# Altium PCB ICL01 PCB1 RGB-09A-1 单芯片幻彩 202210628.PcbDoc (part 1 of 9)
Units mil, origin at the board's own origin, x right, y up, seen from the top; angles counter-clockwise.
Board outline 17436.43 x 6581.89 mil, 2 copper layers (Top Layer, Bottom Layer), stack 65.792 mil thick; 425 components, 516 nets, 1625 pads, 2772 vias.
Unrouted connection lines stored in the file: 1.
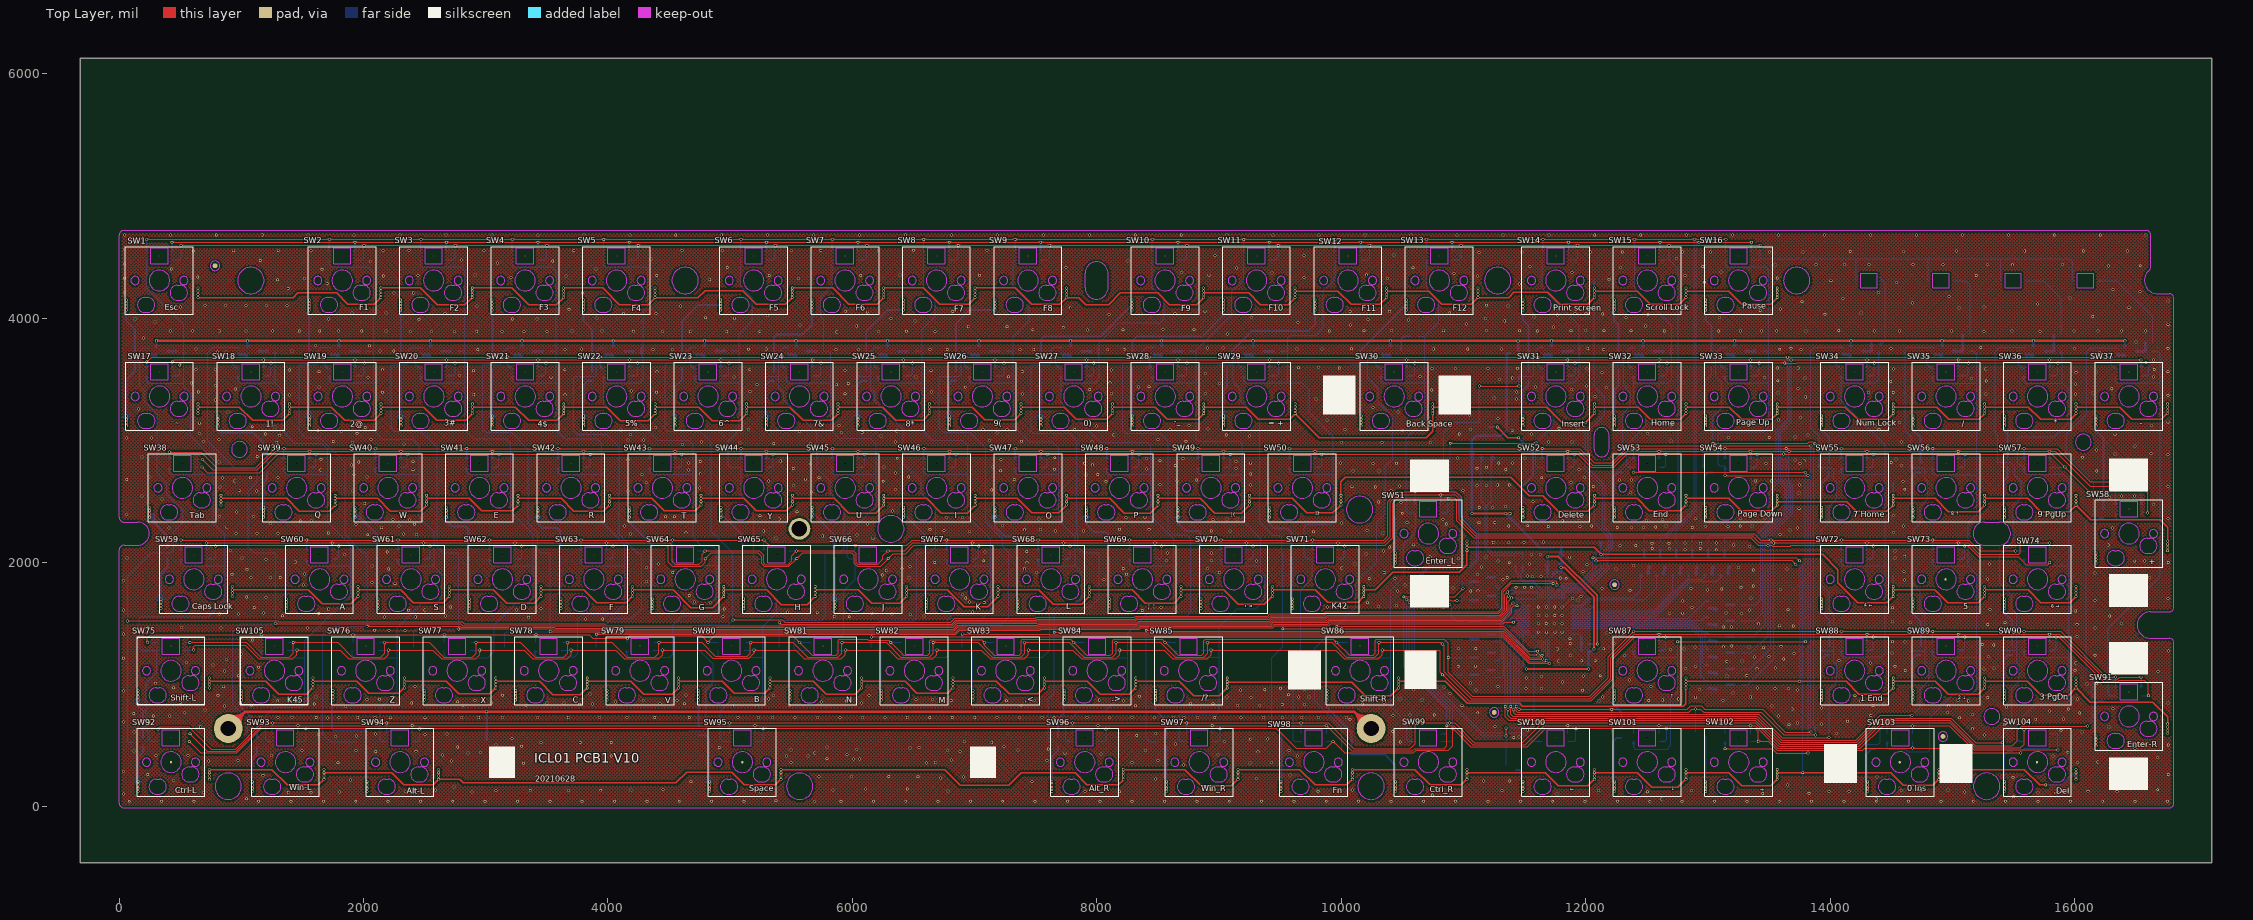
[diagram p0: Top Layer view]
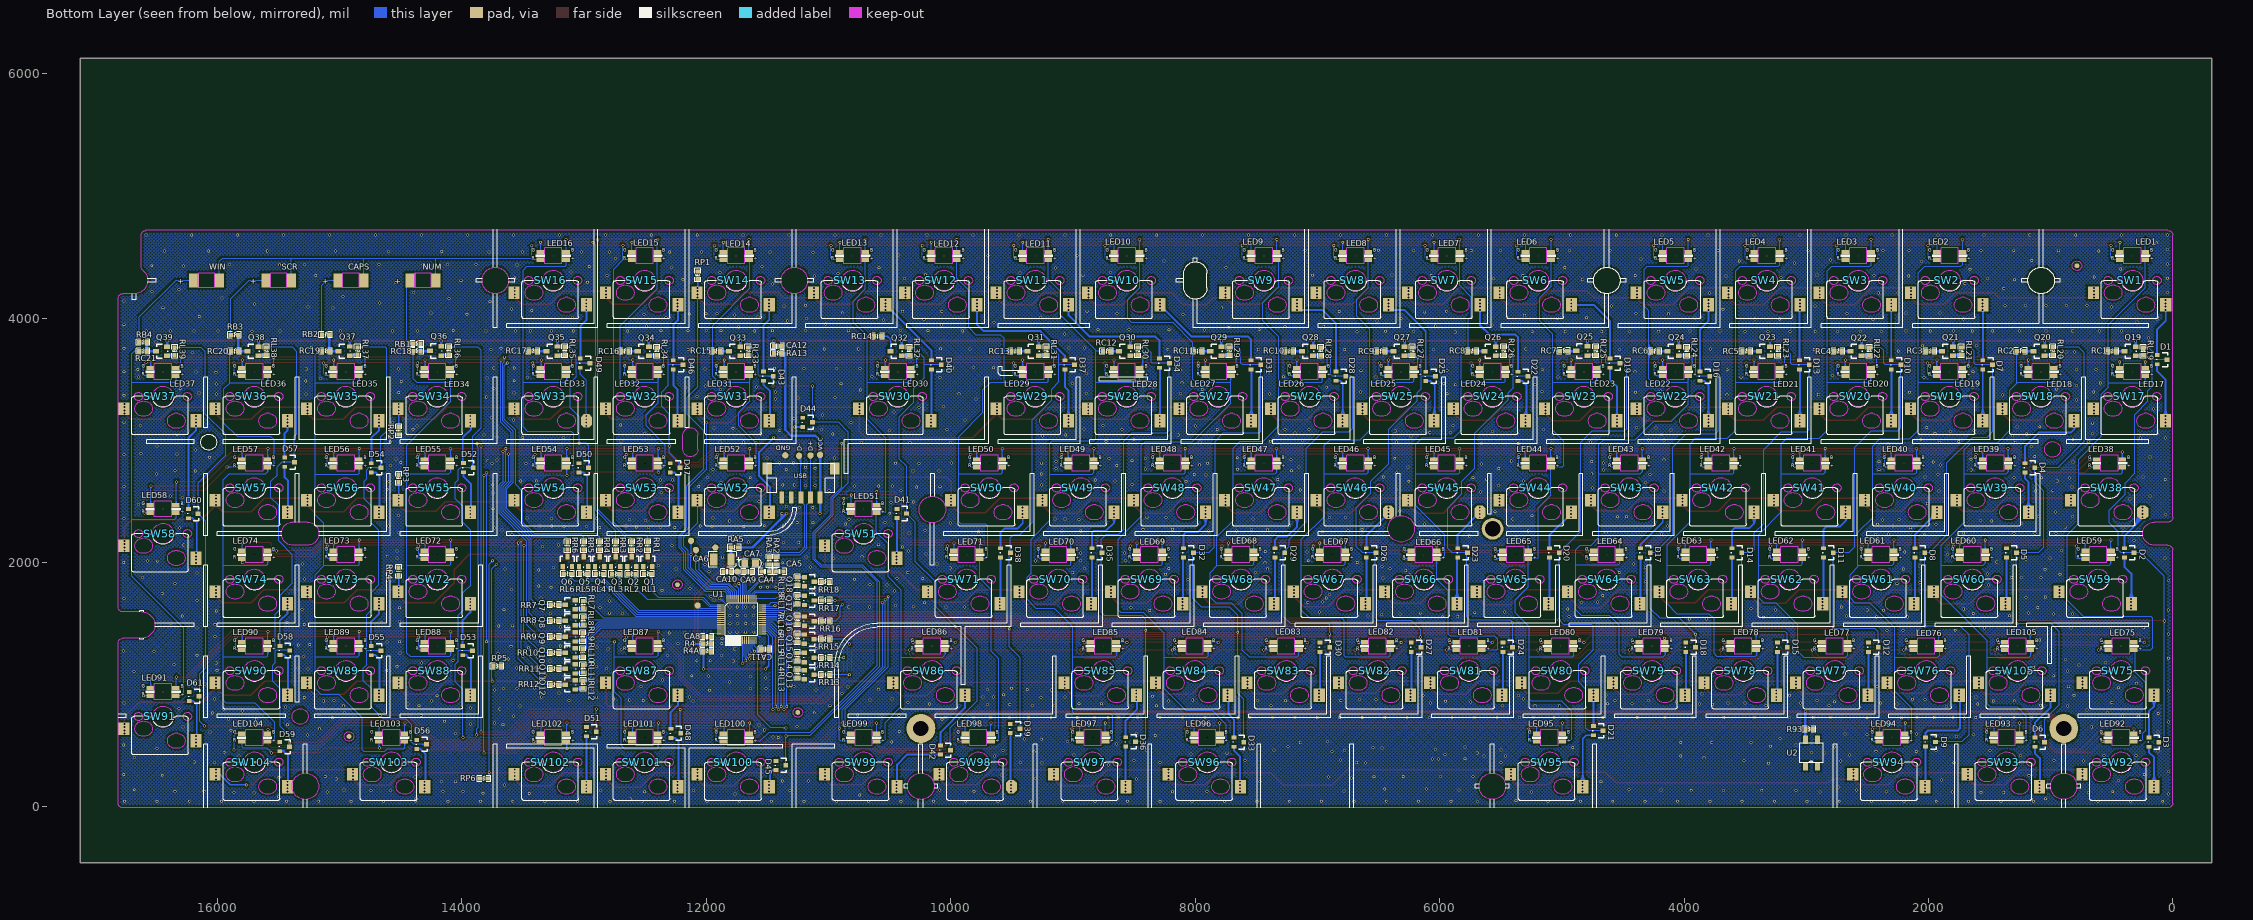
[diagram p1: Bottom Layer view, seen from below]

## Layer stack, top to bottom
Top Solder: solder mask 0.4, Solder Resist, Dk 3.5
Top Layer: signal copper 1.4
Dielectric 1: dielectric 62.9921, FR-4, Dk 4.8
Bottom Layer: signal copper 1.4
Bottom Solder: solder mask 0.4, Solder Resist, Dk 3.5

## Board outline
-315.78,-457.77 -315.78,6124.12 17120.64,6124.12 17120.64,-457.77

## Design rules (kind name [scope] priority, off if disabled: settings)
Clearance [All] p1: gap=6
ComponentClearance [All] p1 off: gap=10 collisioncheckmode=3 verticalgap=10 showdistances=FALSE
DiffPairsRouting [All] p1: maxlimit=9.84 minlimit=9.84 mostfreqgap=9.84 toplayer_minwidth=9.84 toplayer_maxwidth=9.84 toplayer_prefwidth=9.84 bottomlayer_minwidth=9.84 bottomlayer_maxwidth=9.84 bottomlayer_prefwidth=9.84 maxuncoupledlength=500
PlaneClearance [All] p1: clearance=19.68
PolygonConnect PolygonConnect_1 [ISVIA] p1: connectstyle=Direct reliefconductorwidth=10 reliefentries=4 polygonreliefangle="90 Angle" airgapwidth=10
PolygonConnect [All] p2: connectstyle=Relief reliefconductorwidth=10 reliefentries=4 polygonreliefangle="90 Angle" airgapwidth=10
RoutingVias [All] p1: holewidth=15.75 width=23.62 viastyle="Through Hole" minholewidth=15.75 minwidth=23.62 maxholewidth=15.75 maxwidth=23.62
SolderMaskExpansion [All] p1: expansion=4
Width [All] p1: maxlimit=78.74 minlimit=7.87 preferedwidth=9.84
26 further rules are at their usual default settings.

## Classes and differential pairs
component class WT6576F方案V1.0_Main: CN1
differential pair NewDifferentialPair1: +NetCONA1_3 -NetCONA1_4
differential pair NewDifferentialPair2: +D- -D+

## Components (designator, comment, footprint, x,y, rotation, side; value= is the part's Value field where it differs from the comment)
CA4 "22pF NPO材质" 0603C 11516.69,1925.53 r0 bottom
CA5 "22pF NPO材质" 0603C 11398.37,1926.51 r180 bottom
CA6 "SMD-B型-47uF±10%/10V 坦电容" 1210 11799.03,2024.68 r0 bottom
CA7 "22uF±10%/10V" 0805-C 11685.76,1994.25 r180 bottom
CA8 "0.1uF/+80%-20%/25V" 0603C 11993.11,1391.62 r180 bottom
CA9 "0.1uF/+80%-20%/25V" 0603C 11658.2,1925.35 r180 bottom
CA10 "0.1uF/+80%-20%/25V" 0603C 11828.56,1925.27 r180 bottom
CA11 "0.1uF/+80%-20%/25V" 0603C 11519.84,1289.57 r180 bottom
CA12 "0.1uF/+80%-20%/25V" 0603C 11416.72,3770 r0 bottom
CAPS "6028 white" 6028#1 14902.54,4307.08 r0 top
D1 "" BAV70A-SOT-23 89.23,3659.22 r270 bottom
D2 "" BAV70A-SOT-23 357.95,2079.44 r270 bottom
D3 "" BAV70A-SOT-23 156.69,530.53 r270 bottom
D4 "" BAV70A-SOT-23 1170.31,2775.01 r270 bottom
D5 "" BAV70A-SOT-23 1321.48,2079.44 r270 bottom
D6 "" BAV70A-SOT-23 1090,530 r270 bottom
D7 "" BAV70A-SOT-23 1515.75,3616.87 r270 bottom
D8 "" BAV70A-SOT-23 2070.61,2079.44 r270 bottom
D9 "" BAV70A-SOT-23 1983.64,531.43 r270 bottom
D10 "" BAV70A-SOT-23 2265.38,3616.87 r270 bottom
D11 "" BAV70A-SOT-23 2819.8,2079.44 r270 bottom
D12 "" BAV70A-SOT-23 2451.9,1306.47 r270 bottom
D13 "" BAV70A-SOT-23 3016.25,3616.87 r270 bottom
D14 "" BAV70A-SOT-23 3568.64,2079.44 r270 bottom
D15 "" BAV70A-SOT-23 3196.32,1306.47 r270 bottom
D16 "" BAV70A-SOT-23 3830.04,3524.02 r270 bottom
D17 "" BAV70A-SOT-23 4316.47,2079.44 r270 bottom
D18 "" BAV70A-SOT-23 3945.77,1306.47 r270 bottom
D19 "" BAV70A-SOT-23 4565.63,3630.32 r270 bottom
D20 "" BAV70A-SOT-23 5061.98,2079.44 r270 bottom
D21 "" BAV70A-SOT-23 4702.33,623.75 r270 bottom
D22 "" BAV70A-SOT-23 5318.17,3523.23 r270 bottom
D23 "" BAV70A-SOT-23 5812.19,2079.44 r270 bottom
D24 "" BAV70A-SOT-23 5442.79,1306.47 r270 bottom
D25 "" BAV70A-SOT-23 6074.13,3523.04 r270 bottom
D26 "" BAV70A-SOT-23 6559.67,2079.44 r270 bottom
D27 "" BAV70A-SOT-23 6191.5,1306.47 r270 bottom
D28 "" BAV70A-SOT-23 6808.51,3524.33 r270 bottom
D29 "" BAV70A-SOT-23 7307.76,2079.44 r270 bottom
D30 "" BAV70A-SOT-23 6938.85,1306.47 r270 bottom
D31 "" BAV70A-SOT-23 7503.87,3617.26 r270 bottom
D32 "" BAV70A-SOT-23 8054.77,2079.44 r270 bottom
D33 "" BAV70A-SOT-23 7642.81,530.23 r270 bottom
D34 "" BAV70A-SOT-23 8251.3,3630.16 r270 bottom
D35 "" BAV70A-SOT-23 8803.66,2079.44 r270 bottom
D36 "" BAV70A-SOT-23 8528.54,532.29 r270 bottom
D37 "" BAV70A-SOT-23 9026.26,3616.87 r270 bottom
D38 "" BAV70A-SOT-23 9551.76,2079.44 r270 bottom
D39 "" BAV70A-SOT-23 9472.75,641.2 r270 bottom
D40 "" BAV70A-SOT-23 10118.34,3616.87 r270 bottom
D41 "" BAV70A-SOT-23 10400.8,2400.65 r270 bottom
D42 "" BAV70A-SOT-23 10043,465.17 r270 bottom
D43 "" BAV70A-SOT-23 11492.69,3523.97 r270 bottom
D44 "" BAV70A-SOT-23 11170.03,3146.24 r270 bottom
D45 "" BAV70A-SOT-23 11389.12,339.63 r270 bottom
D46 "" BAV70A-SOT-23 12229.77,3616.87 r270 bottom
D47 "" BAV70A-SOT-23 12255.59,2775.01 r270 bottom
D48 "" BAV70A-SOT-23 12248.72,601.95 r270 bottom
D49 "" BAV70A-SOT-23 12990.83,3630.32 r270 bottom
D50 "" BAV70A-SOT-23 13002.64,2775.01 r270 bottom
D51 "" BAV70A-SOT-23 12939.64,615.69 r270 bottom
D52 "" BAV70A-SOT-23 13946.22,2775.51 r270 bottom
D53 "" BAV70A-SOT-23 13952.09,1278.94 r270 bottom
D54 "" BAV70A-SOT-23 14701.46,2775.01 r270 bottom
D55 "" BAV70A-SOT-23 14701.1,1278.94 r270 bottom
D56 "" BAV70A-SOT-23 14328.42,511.23 r270 bottom
D57 "" BAV70A-SOT-23 15409.4,2820.65 r270 bottom
D58 "" BAV70A-SOT-23 15448.15,1279.93 r270 bottom
D59 "" BAV70A-SOT-23 15450.47,493.51 r270 bottom
D60 "" BAV70A-SOT-23 16197.52,2400.01 r270 bottom
D61 "" BAV70A-SOT-23 16190.63,903.94 r270 bottom
LED1 "Esc" "LED 6028RGBA" 330.34,4508.07 r180 bottom
LED2 "F1" "LED RGB" 1826.4,4508.07 r180 bottom
LED3 "F2" "LED RGB" 2574.43,4508.07 r180 bottom
LED4 "F3" "LED RGB" 3322.46,4508.07 r180 bottom
LED5 "F4" "LED RGB" 4070.5,4508.07 r180 bottom
LED6 "F5" "LED RGB" 5192.54,4508.07 r180 bottom
LED7 "F6" "LED RGB" 5940.57,4508.07 r180 bottom
LED8 "F7" "LED RGB" 6688.61,4508.07 r180 bottom
LED9 "F8" "LED RGB" 7436.64,4508.07 r180 bottom
LED10 "F9" "LED RGB" 8558.69,4508.07 r180 bottom
LED11 "F10" "LED RGB" 9306.72,4508.07 r180 bottom
LED12 "F11" "LED RGB" 10054.75,4508.07 r180 bottom
LED13 "Print screen" "LED RGB" 10802.78,4508.07 r180 bottom
LED14 "F12" "LED RGB" 11755.54,4508.07 r180 bottom
LED15 "Scroll Lock" "LED RGB" 12503.57,4508.07 r180 bottom
LED16 "Pause" "LED RGB" 13251.6,4508.07 r180 bottom
LED17 "` ~" "LED RGB" 331.32,3559.25 r180 bottom
LED18 "1!" "LED RGB" 1079.36,3559.25 r180 bottom
LED19 "2@" "LED RGB" 1827.39,3559.25 r180 bottom
LED20 "3#" "LED RGB" 2575.42,3559.25 r180 bottom
LED21 "4$" "LED RGB" 3323.45,3559.25 r180 bottom
LED22 "5%" "LED RGB" 4071.48,3559.25 r180 bottom
LED23 "6^" "LED RGB" 4819.51,3559.25 r180 bottom
LED24 "7&" "LED RGB" 5567.54,3559.25 r180 bottom
LED25 "8*" "LED RGB" 6315.58,3559.25 r180 bottom
LED26 "9(" "LED RGB" 7063.61,3559.25 r180 bottom
LED27 "0)" "LED RGB" 7811.64,3559.25 r180 bottom
LED28 "-_" "LED RGB" 8559.67,3559.25 r180 bottom
LED29 "=+" "LED RGB" 9307.7,3559.25 r180 bottom
LED30 "Back Space" "LED RGB" 10432.7,3559.25 r180 bottom
LED31 "Insert" "LED RGB" 11755.54,3559.25 r180 bottom
LED32 "Home" "LED RGB" 12503.57,3559.25 r180 bottom
LED33 "Page Up" "LED RGB" 13251.6,3559.25 r180 bottom
LED34 "Num Lock" "LED RGB" 14200.42,3559.25 r180 bottom
LED35 "/" "LED RGB" 14948.45,3559.25 r180 bottom
LED36 "*" "LED RGB" 15696.48,3559.25 r180 bottom
LED37 "-" "LED RGB" 16444.51,3559.25 r180 bottom
LED38 "Tab" "LED RGB" 518.33,2811.22 r180 bottom
LED39 "Q" "LED RGB" 1453.37,2811.22 r180 bottom
LED40 "W" "LED RGB" 2201.4,2811.22 r180 bottom
LED41 "E" "LED RGB" 2949.43,2811.22 r180 bottom
LED42 "R" "LED RGB" 3697.47,2811.22 r180 bottom
LED43 "T" "LED RGB" 4445.5,2811.22 r180 bottom
LED44 "Y" "LED RGB" 5193.53,2811.22 r180 bottom
LED45 "U" "LED RGB" 5941.56,2811.22 r180 bottom
LED46 "I" "LED RGB" 6689.59,2811.22 r180 bottom
LED47 "O" "LED RGB" 7437.62,2811.22 r180 bottom
LED48 "P" "LED RGB" 8185.65,2811.22 r180 bottom
LED49 "[{" "LED RGB" 8933.69,2811.22 r180 bottom
LED50 "]}" "LED RGB" 9681.72,2811.22 r180 bottom
LED51 "Enter_L" "LED RGB" 10712.23,2437.21 r180 bottom
LED52 "Delete" "LED RGB" 11755.54,2811.22 r180 bottom
LED53 "End" "LED RGB" 12503.57,2811.22 r180 bottom
LED54 "Page Down" "LED RGB" 13251.6,2811.22 r180 bottom
LED55 "7 Home" "LED RGB" 14200.42,2811.22 r180 bottom
LED56 "8↑" "LED RGB" 14948.45,2811.22 r180 bottom
LED57 "9 Pgup" "LED RGB" 15696.48,2811.22 r180 bottom
LED58 "+" "LED RGB" 16444.51,2437.21 r180 bottom
LED59 "Caps Lock" "LED RGB" 611.84,2063.19 r180 bottom
LED60 "A" "LED RGB" 1640.38,2063.19 r180 bottom
LED61 "S" "LED RGB" 2388.41,2063.19 r180 bottom
LED62 "D" "LED RGB" 3136.44,2063.19 r180 bottom
LED63 "F" "LED RGB" 3884.47,2063.19 r180 bottom
LED64 "G" "LED RGB" 4632.5,2063.19 r180 bottom
LED65 "H" "LED RGB" 5380.54,2063.19 r180 bottom
LED66 "J" "LED RGB" 6128.57,2063.19 r180 bottom
LED67 "K" "LED RGB" 6876.6,2063.19 r180 bottom
LED68 "L" "LED RGB" 7624.63,2063.19 r180 bottom
LED69 ";:" "LED RGB" 8372.66,2063.19 r180 bottom
LED70 "' \"" "LED RGB" 9120.69,2063.19 r180 bottom
LED71 "K42" "LED RGB" 9868.73,2063.19 r180 bottom
LED72 "4 ←" "LED RGB" 14200.42,2063.19 r180 bottom
LED73 "5" "LED RGB" 14948.45,2063.19 r180 bottom
LED74 "6 →" "LED RGB" 15696.48,2063.19 r180 bottom
LED75 "Shift-L" "LED RGB" 424.83,1315.16 r180 bottom
LED76 "Z" "LED RGB" 2019.32,1315.16 r180 bottom
LED77 "X" "LED RGB" 2767.35,1315.16 r180 bottom
LED78 "C" "LED RGB" 3515.38,1315.16 r180 bottom
LED79 "V" "LED RGB" 4263.41,1315.16 r180 bottom
LED80 "B" "LED RGB" 5011.44,1315.16 r180 bottom
LED81 "N" "LED RGB" 5759.47,1315.16 r180 bottom
LED82 "M" "LED RGB" 6507.5,1315.16 r180 bottom
LED83 ",<" "LED RGB" 7255.54,1315.16 r180 bottom
LED84 ".>" "LED RGB" 8003.57,1315.16 r180 bottom
LED85 "/?" "LED RGB" 8751.6,1315.16 r180 bottom
LED86 "Shift-R" "LED RGB" 10153.17,1315.16 r180 bottom
LED87 "↑" "LED RGB" 12503.57,1315.16 r180 bottom
LED88 "1 End" "LED RGB" 14200.42,1315.16 r180 bottom
LED89 "2↓" "LED RGB" 14948.45,1315.16 r180 bottom
LED90 "3 PgDn" "LED RGB" 15696.48,1315.16 r180 bottom
LED91 "Enter-R" "LED RGB" 16444.51,941.14 r180 bottom
LED92 "Ctrl-L" "LED RGB" 424.83,567.13 r180 bottom
LED93 "Win-L" "LED RGB" 1359.87,567.13 r180 bottom
LED94 "Alt-L" "LED RGB" 2298.84,567.13 r180 bottom
LED95 "Space" "LED RGB" 5100.02,567.13 r180 bottom
LED96 "ALT_R" "LED RGB" 7901.21,567.13 r180 bottom
LED97 "Win_R" "LED RGB" 8838.21,567.13 r180 bottom
LED98 "Fn" "LED RGB" 9775.22,567.13 r180 bottom
LED99 "Ctrl-R" "LED RGB" 10712.23,567.13 r180 bottom
LED100 "←" "LED RGB" 11755.54,567.13 r180 bottom
LED101 "↓" "LED RGB" 12503.57,567.13 r180 bottom
LED102 "→" "LED RGB" 13251.6,567.13 r180 bottom
LED103 "0 Ins" "LED RGB" 14574.43,567.13 r180 bottom
LED104 ".Del" "LED RGB" 15696.48,567.13 r180 bottom
LED105 "K45" "LED RGB" 1271.28,1315.16 r180 bottom
NUM "6028 white" 6028#2 14311.99,4307.08 r0 top
Q1 "8050" "SOT-23 NPN" 12479.51,2007.65 r180 bottom
Q2 "8050" "SOT-23 NPN" 12610.42,2007.65 r180 bottom
Q3 "8050" "SOT-23 NPN" 12742.31,2007.65 r180 bottom
Q4 "8050" "SOT-23 NPN" 12873.22,2007.65 r180 bottom
Q5 "8050" "SOT-23 NPN" 13004.12,2007.65 r180 bottom
Q6 "8050" "SOT-23 NPN" 13136.01,2007.65 r180 bottom
Q7 "8050" "SOT-23 NPN" 13112.87,1653.94 r90 bottom
Q8 "8050" "SOT-23 NPN" 13113.23,1522.54 r90 bottom
Q9 "8050" "SOT-23 NPN" 13113.23,1390.65 r90 bottom
Q10 "8050" "SOT-23 NPN" 13113.23,1259.74 r90 bottom
Q11 "8050" "SOT-23 NPN" 13113.23,1128.84 r90 bottom
Q12 "8050" "SOT-23 NPN" 13113.23,997.93 r90 bottom
Q13 "8050" "SOT-23 NPN" 11159.23,1082.4 r270 bottom
Q14 "8050" "SOT-23 NPN" 11158.87,1222.69 r270 bottom
Q15 "8050" "SOT-23 NPN" 11159.23,1373.5 r270 bottom
Q16 "8050" "SOT-23 NPN" 11156.58,1520.75 r270 bottom
Q17 "8050" "SOT-23 NPN" 11156.58,1689.8 r270 bottom
Q18 "8050" "SOT-23 NPN" 11156.58,1842.5 r270 bottom
Q19 "8550" "SOT-23 PNP" 345.16,3728.25 r90 bottom
Q20 "8550" "SOT-23 PNP" 1090.24,3729.23 r90 bottom
Q21 "8550" "SOT-23 PNP" 1839.25,3728.25 r90 bottom
Q22 "8550" "SOT-23 PNP" 2588.27,3728.25 r90 bottom
Q23 "8550" "SOT-23 PNP" 3337.28,3728.25 r90 bottom
Q24 "8550" "SOT-23 PNP" 4084.33,3728.25 r90 bottom
Q25 "8550" "SOT-23 PNP" 4831.38,3730.22 r90 bottom
Q26 "8550" "SOT-23 PNP" 5580.39,3728.25 r90 bottom
Q27 "8550" "SOT-23 PNP" 6326.46,3728.25 r90 bottom
Q28 "8550" "SOT-23 PNP" 7075.47,3728.25 r90 bottom
Q29 "8550" "SOT-23 PNP" 7825.47,3728.25 r90 bottom
Q30 "8550" "SOT-23 PNP" 8571.53,3728.25 r90 bottom
Q31 "8550" "SOT-23 PNP" 9319.57,3728.25 r90 bottom
Q32 "8550" "SOT-23 PNP" 10441.61,3728.25 r90 bottom
Q33 "8550" "SOT-23 PNP" 11761.5,3728.25 r90 bottom
Q34 "8550" "SOT-23 PNP" 12509.53,3728.25 r90 bottom
Q35 "8550" "SOT-23 PNP" 13257.56,3729.23 r90 bottom
Q36 "8550" "SOT-23 PNP" 14209.33,3730.22 r90 bottom
Q37 "8550" "SOT-23 PNP" 14956.38,3729.23 r90 bottom
Q38 "8550" "SOT-23 PNP" 15703.42,3728.25 r90 bottom
Q39 "8550" "SOT-23 PNP" 16452.44,3728.25 r90 bottom
R4 "0R" 0603R#1 11993.06,1332.8 r180 bottom
R4A "NC" 0603R#1 11993.06,1275.09 r180 bottom
R93 "NC" 0603R#2 2976.53,635.24 r0 bottom
RA2 "22R±5%" 0603R#1 11427.9,2013.13 r270 bottom
RA3 "22R±5%" 0603R#1 11485.97,2013.13 r270 bottom
RA5 "0R" 0603R#1 11770.11,2122.2 r0 bottom
RA13 "0R" 0603R#1 11415.93,3711.42 r180 bottom
RB1 "151R±5%" 0603R#1 14366.81,3788.79 r180 bottom
RB2 "151R±5%" 0603R#1 15113.86,3863.59 r180 bottom
RB3 "151±5%" 0603R#1 15858.94,3861.62 r180 bottom
RB4 "151R±5%" 0603R#1 16607.95,3802.57 r180 bottom
RC1 "10R±5%" 0603R#1 498.7,3729.23 r180 bottom
RC2 "10R±5%" 0603R#1 1246.73,3730.22 r180 bottom
RC3 "10R±5%" 0603R#1 1987.87,3729.23 r180 bottom
RC4 "10R±5%" 0603R#1 2739.84,3729.23 r180 bottom
RC5 "10R±5%" 0603R#1 3491.81,3729.23 r180 bottom
RC6 "10R±5%" 0603R#1 4238.86,3729.23 r180 bottom
RC7 "10R±5%" 0603R#1 4983.94,3730.72 r180 bottom
RC8 "10R±5%" 0603R#1 5733.94,3728.75 r180 bottom
RC9 "10R±5%" 0603R#1 6481.97,3728.25 r180 bottom
RC10 "10R±5%" 0603R#1 7231.97,3728.25 r180 bottom
RC11 "10R±5%" 0603R#1 7980.98,3729.23 r180 bottom
RC12 "10R±5%" 0603R#1 8724.09,3728.75 r180 bottom
RC13 "10R±5%" 0603R#1 9474.09,3728.25 r180 bottom
RC14 "10R±5%" 0603R#1 10599.03,3851.22 r180 bottom
RC15 "10R±5%" 0603R#1 11917.01,3729.23 r180 bottom
RC16 "10R±5%" 0603R#1 12665.52,3728.75 r180 bottom
RC17 "10R±5%" 0603R#1 13416.51,3729.73 r180 bottom
RC18 "10R±5%" 0603R#1 14366.81,3730.22 r180 bottom
RC19 "10R±5%" 0603R#1 15112.87,3729.73 r180 bottom
RC20 "10R±5%" 0603R#1 15857.95,3728.25 r180 bottom
RC21 "10R±5%" 0603R#1 16608.44,3728.75 r180 bottom
RL1 "1K±5%" 0603R#1 12480.5,1906.27 r0 bottom
RL2 "1K±5%" 0603R#1 12610.42,1905.28 r0 bottom
RL3 "1K±5%" 0603R#1 12742.31,1905.28 r0 bottom
RL4 "1K±5%" 0603R#1 12874.2,1906.27 r0 bottom
RL5 "1K±5%" 0603R#1 13004.12,1907.25 r0 bottom
RL6 "1K±5%" 0603R#1 13136.01,1906.27 r0 bottom
RL7 "1K±5%" 0603R#1 13008.54,1653.94 r270 bottom
RL8 "1K±5%" 0603R#1 13008.9,1522.54 r270 bottom
RL9 "1K±5%" 0603R#1 13010.03,1391.01 r270 bottom
RL10 "1K±5%" 0603R#1 13011.85,1258.76 r270 bottom
RL11 "1K±5%" 0603R#1 13008.9,1128.84 r270 bottom
RL12 "1K±5%" 0603R#1 13007.91,1001.87 r270 bottom
RL13 "1K±5%" 0603R#1 11254.76,1090.17 r90 bottom
RL14 "1K±5%" 0603R#1 11254.76,1230.8 r90 bottom
RL15 "1K±5%" 0603R#1 11254.76,1381.42 r90 bottom
RL16 "1K±5%" 0603R#1 11254.76,1528.94 r90 bottom
RL17 "1K±5%" 0603R#1 11254.76,1698.01 r90 bottom
RL18 "1K±5%" 0603R#1 11254.76,1848.75 r90 bottom
RL19 "1K±5%" 0603R#1 242.79,3726.78 r270 bottom
RL20 "1K±5%" 0603R#1 984.92,3729.23 r270 bottom
RL21 "1K±5%" 0603R#1 1731.97,3728.25 r270 bottom
RL22 "1K±5%" 0603R#1 2485.9,3727.26 r270 bottom
RL23 "1K±5%" 0603R#1 3231.97,3727.26 r270 bottom
RL24 "1K±5%" 0603R#1 3978.03,3727.26 r270 bottom
RL25 "1K±5%" 0603R#1 4722.12,3729.23 r270 bottom
RL26 "1K±5%" 0603R#1 5475.08,3729.23 r270 bottom
RL27 "1K±5%" 0603R#1 6223.11,3728.25 r270 bottom
RL28 "1K±5%" 0603R#1 6973.11,3727.26 r270 bottom
RL29 "1K±5%" 0603R#1 7720.16,3728.25 r270 bottom
RL30 "1K±5%" 0603R#1 8469.17,3728.25 r270 bottom
RL31 "1K±5%" 0603R#1 9218.19,3728.25 r270 bottom
RL32 "1K±5%" 0603R#1 10339.25,3727.26 r270 bottom
RL33 "1K±5%" 0603R#1 11658.15,3728.25 r270 bottom
RL34 "1K±5%" 0603R#1 12404.21,3727.26 r270 bottom
RL35 "1K±5%" 0603R#1 13157.16,3730.22 r270 bottom
RL36 "1K±5%" 0603R#1 14105.98,3730.22 r270 bottom
RL37 "1K±5%" 0603R#1 14853.03,3728.25 r270 bottom
RL38 "1K±5%" 0603R#1 15601.06,3728.25 r270 bottom
RL39 "1K±5%" 0603R#1 16350.08,3727.26 r270 bottom
RP1 "100K±5%" 0603R#1 12070.55,4349.81 r270 bottom
RP2 "100K±5%" 0603R#1 14516.3,3077.66 r90 bottom
RP3 "100K±5%" 0603R#1 14517.4,2687.41 r270 bottom
RP4 "100K±5%" 0603R#1 14517.4,1925.6 r270 bottom
RP5 "100K±5%" 0603R#1 13712.28,1150.01 r0 bottom
RP6 "100K±5%" 0603R#1 13817.9,232.19 r180 bottom
RR1 "151R±5%" 0603R#1 12479.13,2136.29 r90 bottom
RR2 "10R±5%" 0603R#1 12609.95,2136.29 r90 bottom
RR3 "10R±5%" 0603R#1 12741.82,2136.29 r90 bottom
RR4 "151R±5%" 0603R#1 12872.88,2136.29 r90 bottom
RR5 "10R±5%" 0603R#1 13003.66,2136.29 r90 bottom
RR6 "10R±5%" 0603R#1 13135.83,2136.29 r90 bottom
RR7 "151R±5%" 0603R#1 13243.03,1654.34 r0 bottom
RR8 "10R±5%" 0603R#1 13243.03,1522.89 r0 bottom
RR9 "10R±5%" 0603R#1 13243.03,1391.03 r0 bottom
RR10 "151R±5%" 0603R#1 13243.03,1260.15 r0 bottom
RR11 "10R±5%" 0603R#1 13243.03,1129.22 r0 bottom
RR12 "10R±5%" 0603R#1 13243.03,998.41 r0 bottom
RR13 "82R±5%" 0603R#1 11024.39,1081.74 r180 bottom
RR14 "10R±5%" 0603R#1 11024.41,1221.77 r180 bottom
RR15 "10R±5%" 0603R#1 11024.86,1372.92 r180 bottom
RR16 "82R±5%" 0603R#1 11024.85,1520.07 r180 bottom
RR17 "10R±5%" 0603R#1 11024.81,1689.09 r180 bottom
RR18 "10R±5%" 0603R#1 11024.91,1841.77 r180 bottom
SCR "6028 white" 6028#1 15493.09,4307.08 r0 top
SW1 "Esc" CJ-SW2A#1 330.78,4307.08 r0 top locked
SW2 "F1" CJ-SW2A#1 1826.84,4307.08 r0 top locked
SW3 "F2" CJ-SW2A#1 2574.87,4307.08 r0 top locked
SW4 "F3" CJ-SW2A#1 3322.9,4307.08 r0 top locked
SW5 "F4" CJ-SW2A#1 4070.94,4307.08 r0 top locked
SW6 "F5" CJ-SW2A#1 5192.98,4307.08 r0 top locked
SW7 "F6" CJ-SW2A#1 5941.02,4307.08 r0 top locked
SW8 "F7" CJ-SW2A#1 6689.05,4307.08 r0 top locked
SW9 "F8" CJ-SW2A#1 7437.08,4307.08 r0 top locked
SW10 "F9" CJ-SW2A#1 8559.13,4307.08 r0 top locked
SW11 "F10" CJ-SW2A#1 9307.16,4307.08 r0 top locked
SW12 "F11" CJ-SW2A#1 10055.19,4307.08 r0 top locked
SW13 "F12" CJ-SW2A#1 10803.22,4307.08 r0 top locked
SW14 "Print screen" CJ-SW2A#1 11755.98,4307.08 r0 top locked
SW15 "Scroll Lock" CJ-SW2A#1 12504.01,4307.08 r0 top locked
SW16 "Pause" CJ-SW2A#1 13252.04,4307.08 r0 top locked
SW17 "` ~" CJ-SW2A#1 331.76,3358.27 r0 top
SW18 "1!" CJ-SW2A#1 1079.8,3358.27 r0 top
SW19 "2@" CJ-SW2A#1 1827.83,3358.27 r0 top locked
SW20 "3#" CJ-SW2A#1 2575.86,3358.27 r0 top locked
SW21 "4$" CJ-SW2A#1 3323.89,3358.27 r0 top locked
SW22 "5%" CJ-SW2A#1 4071.92,3358.27 r0 top locked
SW23 "6^" CJ-SW2A#1 4819.95,3358.27 r0 top locked
SW24 "7&" CJ-SW2A#1 5567.98,3358.27 r0 top locked
SW25 "8*" CJ-SW2A#1 6316.02,3358.27 r0 top locked
SW26 "9(" CJ-SW2A#1 7064.05,3358.27 r0 top locked
SW27 "0)" CJ-SW2A#1 7812.08,3358.27 r0 top locked
SW28 "-_" CJ-SW2A#1 8560.11,3358.27 r0 top locked
SW29 "= +" CJ-SW2A#1 9308.14,3358.27 r0 top locked
SW30 "Back Space" CJ-SW2A#1 10433.14,3358.27 r0 top locked
SW31 "Insert" CJ-SW2A#1 11755.98,3358.27 r0 top locked
SW32 "Home" CJ-SW2A#1 12504.01,3358.27 r0 top locked
SW33 "Page Up" CJ-SW2A#2 13252.04,3358.27 r0 top locked
SW34 "Num Lock" CJ-SW2A#1 14200.86,3358.27 r0 top locked
SW35 "/" CJ-SW2A#1 14948.89,3358.27 r0 top locked
SW36 "*" CJ-SW2A#1 15696.92,3358.27 r0 top locked
SW37 "-" CJ-SW2A#1 16444.95,3358.27 r0 top locked
SW38 "Tab" CJ-SW2A#2 518.77,2610.23 r0 top
SW39 "Q" CJ-SW2A#1 1453.81,2610.23 r0 top
SW40 "W" CJ-SW2A#1 2201.84,2610.23 r0 top locked
SW41 "E" CJ-SW2A#1 2949.87,2610.23 r0 top locked
SW42 "R" CJ-SW2A#1 3697.91,2610.23 r0 top locked
SW43 "T" CJ-SW2A#1 4445.94,2610.23 r0 top locked
SW44 "Y" CJ-SW2A#1 5193.97,2610.23 r0 top
SW45 "U" CJ-SW2A#2 5942,2610.23 r0 top locked
SW46 "I" CJ-SW2A#2 6690.03,2610.23 r0 top locked
SW47 "O" CJ-SW2A#1 7438.06,2610.23 r0 top locked
SW48 "P" CJ-SW2A#1 8186.09,2610.23 r0 top locked
SW49 "[{" CJ-SW2A#1 8934.12,2610.23 r0 top locked
SW50 "]}" CJ-SW2A#1 9682.16,2610.23 r0 top locked
SW51 "Enter_L" CJ-SW2A#1 10712.67,2236.22 r0 top locked
SW52 "Delete" CJ-SW2A#1 11755.98,2610.23 r0 top locked
SW53 "End" CJ-SW2A#1 12504.01,2610.23 r0 top locked
SW54 "Page Down" CJ-SW2A#1 13252.04,2610.23 r0 top locked
SW55 "7 Home" CJ-SW2A#1 14200.86,2610.23 r0 top locked
SW56 "8 ↑" CJ-SW2A#1 14948.89,2610.23 r0 top locked
SW57 "9 PgUp" CJ-SW2A#1 15696.92,2610.23 r0 top locked
SW58 "+" CJ-SW2A#1 16444.95,2236.22 r0 top locked
SW59 "Caps Lock" CJ-SW2A#1 612.28,1862.2 r0 top
SW60 "A" CJ-SW2A#1 1640.82,1862.2 r0 top
SW61 "S" CJ-SW2A#1 2388.85,1862.2 r0 top locked
SW62 "D" CJ-SW2A#1 3136.88,1862.2 r0 top locked
SW63 "F" CJ-SW2A#1 3884.91,1862.2 r0 top locked
SW64 "G" CJ-SW2A#1 4632.94,1862.2 r0 top locked
SW65 "H" CJ-SW2A#1 5380.98,1862.2 r0 top locked
SW66 "J" CJ-SW2A#1 6129.01,1862.2 r0 top locked
SW67 "K" CJ-SW2A#1 6877.04,1862.2 r0 top locked
SW68 "L" CJ-SW2A#1 7625.07,1862.2 r0 top locked
SW69 "; :" CJ-SW2A#1 8373.1,1862.2 r0 top locked
SW70 "' \"" CJ-SW2A#1 9121.13,1862.2 r0 top locked
SW71 "K42" CJ-SW2A#1 9869.17,1862.2 r0 top locked
SW72 "4 ←" CJ-SW2A#1 14200.86,1862.2 r0 top locked
SW73 "5" CJ-SW2A#1 14948.89,1862.2 r0 top locked
SW74 "6 →" CJ-SW2A#1 15696.92,1862.2 r0 top locked
SW75 "Shift-L" CJ-SW2A#3 425.27,1114.17 r0 top locked
SW76 "Z" CJ-SW2A#1 2019.76,1114.17 r0 top locked
SW77 "X" CJ-SW2A#1 2767.79,1114.17 r0 top locked
SW78 "C" CJ-SW2A#1 3515.82,1114.17 r0 top locked
SW79 "V" CJ-SW2A#1 4263.85,1114.17 r0 top locked
SW80 "B" CJ-SW2A#1 5011.88,1114.17 r0 top locked
SW81 "N" CJ-SW2A#1 5759.91,1114.17 r0 top locked
SW82 "M" CJ-SW2A#1 6507.94,1114.17 r0 top locked
SW83 ",<" CJ-SW2A#1 7255.98,1114.17 r0 top locked
SW84 ".>" CJ-SW2A#1 8004.01,1114.17 r0 top locked
SW85 "/?" CJ-SW2A#1 8752.04,1114.17 r0 top locked
SW86 "Shift-R" CJ-SW2A#1 10153.61,1114.17 r0 top locked
SW87 "↑" CJ-SW2A#1 12504.01,1114.17 r0 top locked
SW88 "1 End" CJ-SW2A#1 14200.86,1114.17 r0 top locked
SW89 "2 ↓" CJ-SW2A#1 14948.89,1114.17 r0 top locked
SW90 "3 PgDn" CJ-SW2A#1 15696.92,1114.17 r0 top locked
SW91 "Enter-R" CJ-SW2A#1 16444.95,740.16 r0 top locked
SW92 "Ctrl-L" CJ-SW2A#1 425.27,366.14 r0 top
SW93 "Win-L" CJ-SW2A#1 1362.27,366.14 r0 top locked
SW94 "Alt-L" CJ-SW2A#1 2299.28,366.14 r0 top locked
SW95 "Space" CJ-SW2A#1 5100.46,366.14 r0 top
SW96 "Alt_R" CJ-SW2A#1 7901.65,366.14 r0 top locked
SW97 "Win_R" CJ-SW2A#1 8838.65,366.14 r0 top locked
SW98 "Fn" CJ-SW2A#2 9775.66,366.14 r0 top locked
SW99 "Ctrl_R" CJ-SW2A#1 10712.67,366.14 r0 top locked
SW100 "←" CJ-SW2A#1 11755.98,366.14 r0 top locked
SW101 "↓" CJ-SW2A#1 12504.01,366.14 r0 top locked
SW102 "→" CJ-SW2A#1 13252.04,366.14 r0 top locked
SW103 "0 Ins" CJ-SW2A#1 14574.87,366.14 r0 top locked
SW104 ".Del" CJ-SW2A#1 15696.92,366.14 r0 top locked
SW105 "K45" CJ-SW2A#1 1271.72,1114.17 r0 top locked
U1 "VS11K09A-1-LQFP64" LQFP64A 11880.59,1651.98 r180 bottom locked
U2 "VS01-SOP-4" ESD 3007.04,549.61 r90 bottom
USB "USB" PCBCOMPONENT_1 10949.96,2570.75 r0 top
WIN "6028 white" 6028#1 16083.64,4307.08 r0 top
? "Comment" Mark点 11251.15,772.93 r0 top
? "Comment" Mark点 14922.57,576.68 r0 top
? "Comment" Mark点 12236.14,1818.59 r0 top
? "Comment" Mark点 785.67,4427.42 r0 top

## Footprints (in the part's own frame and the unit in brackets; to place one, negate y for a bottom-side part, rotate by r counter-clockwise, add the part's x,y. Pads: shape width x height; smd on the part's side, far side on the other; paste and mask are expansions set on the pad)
0603C [mm]
  rect 0.9x0.9 smd: 1(-0.765,-0.012) 2(0.759,-0.012)
  silkscreen extent -1.4,-0.65 1.39,0.62
0603R#1 [mm]
  rect 0.9x0.9 smd: 1(-0.779,-0.005) 2(0.745,-0.005)
  silkscreen extent -1.41,-0.64 1.38,0.63
0603R#2 [mm]
  rect 0.9x0.9 smd: 1(-0.756,0.012) 2(0.768,0.012)
  silkscreen extent -1.39,-0.62 1.4,0.65
0805-C [mm]
  rect 1.4x1.4 smd: 1(-0.009,-0.013) 2(2.231,-0.013)
  silkscreen extent -1.17,-0.86 3.4,0.84
1210 [mil]
  rect 60x100 smd: 1(-0.69,-0.36) 2(140.24,-0.17)
  silkscreen extent -85,-63 181,64
6028#1 [mm]
  round 0 on Bottom Overlay: 0(0,0)
  rect 2x3 smd far side: 1(2.738,0) 2(-2.512,0)
  Keep-Out Layer lines w0.1: -1.581,-1.499 -1.581,1.501 ; -1.578,-1.499 1.822,-1.499 1.822,1.501 ; -1.578,1.499 1.822,1.499
6028#2 [mm]
  round 1.3 on Bottom Overlay: 0(0,0)
  rect 2x3 smd far side: 1(2.738,0) 2(-2.512,0)
  Keep-Out Layer lines w0.1: -1.581,-1.499 -1.581,1.501 ; -1.578,-1.499 1.822,-1.499 1.822,1.501 ; -1.578,1.499 1.822,1.499
BAV70A-SOT-23 [mm]
  round 0.5 on Mech2: 0(0,0)
  rect 0.92x1 smd: A(0,1.016)
  rect 0.8x1 smd: K1(-0.953,-1.016) K2(0.952,-1.016)
  silkscreen extent -1.46,-1.14 1.46,1.14
CJ-SW2A#1 [mm]
  round 0.5 on Top Overlay: 0(0,0)
  rect 2.3x2.6 smd far side: 1(8.15,-2.54)
  rect 2.3x2.8 smd far side: 2(-6.89,-5.08)
  round 0.3 on Top Overlay: 3(-0.011,5.105)
  Keep-Out Layer circle w0.127: c5.079,-0.003 r0.86
  Keep-Out Layer circle w0.127: c-5.079,0.003 r0.86
  Keep-Out Layer circle w0.127: c0,0 r2.15
  Keep-Out Layer lines w0.127: -3.04,-6.63 cw(c-3.04,-5.08) -3.04,-3.53 -2.49,-3.53 cw(c-2.49,-5.08) -2.49,-6.63 -3.04,-6.63 ; 3.75,-4.09 cw(c3.75,-2.54) 3.75,-0.99 4.3,-0.99 cw(c4.3,-2.54) 4.3,-4.09 3.75,-4.09
  silkscreen extent -7.06,-7.03 7.05,7.07
CJ-SW2A#2 [mm]
  round 0.5 on Top Overlay: 0(0,0)
  rect 2.3x2.6 smd far side: 1(8.15,-2.54)
  oct 2.3x2.8 smd far side: 2(-6.89,-5.08)
  round 0.3 on Top Overlay: 3(-0.011,5.105)
  Keep-Out Layer circle w0.127: c5.079,-0.003 r0.86
  Keep-Out Layer circle w0.127: c-5.079,0.003 r0.86
  Keep-Out Layer circle w0.127: c0,0 r2.15
  Keep-Out Layer lines w0.127: -3.04,-6.63 cw(c-3.04,-5.08) -3.04,-3.53 -2.49,-3.53 cw(c-2.49,-5.08) -2.49,-6.63 -3.04,-6.63 ; 3.75,-4.09 cw(c3.75,-2.54) 3.75,-0.99 4.3,-0.99 cw(c4.3,-2.54) 4.3,-4.09 3.75,-4.09
  silkscreen extent -7.06,-7.03 7.05,7.07
CJ-SW2A#3 [mm]
  rect 2.3x2.6 smd far side: 1(8.15,-2.54)
  rect 2.3x2.8 smd far side: 2(-6.89,-5.08)
  round 0.3 on Top Overlay: 3(-0.011,5.105)
  Keep-Out Layer circle w0.127: c5.079,-0.003 r0.86
  Keep-Out Layer circle w0.127: c-5.079,0.003 r0.86
  Keep-Out Layer circle w0.127: c0,0 r2.15
  Keep-Out Layer lines w0.127: -3.04,-6.63 cw(c-3.04,-5.08) -3.04,-3.53 -2.49,-3.53 cw(c-2.49,-5.08) -2.49,-6.63 -3.04,-6.63 ; 3.75,-4.09 cw(c3.75,-2.54) 3.75,-0.99 4.3,-0.99 cw(c4.3,-2.54) 4.3,-4.09 3.75,-4.09
  silkscreen extent -7.06,-7.03 7.05,7.07
ESD [mm]
  rect 1.8x1 smd: 1(-0.008,0.009) 2(-5.51,0.011) 3(-0.008,-2.491) 4(-5.508,-2.491)
  silkscreen extent -4.76,-3.65 -0.76,1.15
"LED 6028RGBA" [mm]
  round 0.2 hole 0.1: 0(0,0)
  rect 1.6x0.9 smd: B(2.65,0.8) G(-2.65,0.8) R(-2.65,-0.8) VDD(2.65,-0.8)
  Keep-Out Layer lines w0.05: 1.8,-1.65 1.8,1.65 -1.8,1.65 -1.8,-1.65 1.8,-1.65
  silkscreen extent -3.68,-0.25 3.68,0.25
"LED RGB" [mm]
  round 0.2 hole 0.1: 0(0,0)
  rect 1.6x0.9 smd: B(2.65,0.8) G(-2.65,0.8) R(-2.65,-0.8) VDD(2.65,-0.8)
  Keep-Out Layer lines w0.05: 1.8,-1.65 -1.8,-1.65 -1.8,1.65 1.8,1.65 1.8,-1.65
  silkscreen extent -3.68,-0.25 3.68,0.25
LQFP64A [mm]
  rect 1.6x0.2 smd: 1(0,0) 2(0,-0.4) 3(0,-0.8) 4(0,-1.2) 5(0,-1.6) 6(0,-2) 7(0,-2.4) 8(0,-2.8) 9(0,-3.2) 10(0,-3.6) 11(0,-4) 12(0,-4.4) 13(0,-4.8) 14(0,-5.2) 15(0,-5.6) 16(0,-6) 33(8.6,-6) 34(8.6,-5.6) 35(8.6,-5.2) 36(8.6,-4.8) 37(8.6,-4.4) 38(8.6,-4) 39(8.6,-3.6) 40(8.6,-3.2) 41(8.6,-2.8) 42(8.6,-2.4) 43(8.6,-2) 44(8.6,-1.6) 45(8.6,-1.2) 46(8.6,-0.8) 47(8.6,-0.4) 48(8.6,0)
  rect 0.2x1.6 smd: 25(4.5,-7.3) 26(4.9,-7.3) 27(5.3,-7.3) 28(5.7,-7.3) 29(6.1,-7.3) 30(6.5,-7.3) 31(6.9,-7.3) 32(7.3,-7.3) 49(7.3,1.3) 50(6.9,1.3) 51(6.5,1.3) 52(6.1,1.3) 53(5.7,1.3) 54(5.3,1.3) 55(4.9,1.3) 56(4.5,1.3) 57(4.1,1.3) 58(3.7,1.3) 59(3.3,1.3) 60(2.9,1.3) 61(2.5,1.3) 62(2.1,1.3) 63(1.7,1.3) 64(1.3,1.3)
  silkscreen extent 0.82,-8.51 7.62,0.38
Mark点 [mm]
  round 1 smd far side: 0(0,0)
  round 1 smd: 0(0,0)
  round 2 on Top Solder: 0(0,0)
  round 2 on Bottom Solder: 0(0,0)
  Keep-Out Layer circle w0.013: c0,0 r1
PCBCOMPONENT_1 [mm]
  rect 2x2.5 smd far side: 0(0,5) 1(14,5)
  rect 1x2.5 smd far side: 1(10.99,-1) 2(9.009,-1) 3(7.01,-1) 4(5.01,-1) 5(3.009,-1)
"SOT-23 NPN" [mil]
  rect 36x43.31 smd: B(-37.5,-40) C(0.5,40) E(37.5,-40)
  silkscreen extent -58,-45 58,45
"SOT-23 PNP" [mil]
  rect 36x47.24 smd: B(-37.5,-40) E(37.5,-40)
  rect 36x50 smd: C(0.5,51.18)
  silkscreen extent -58,-45 58,45

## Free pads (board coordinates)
  round 51.18 smd far side: 2(11069.18,2880.23) 3(11353.79,2876.94) 4(11147.18,2875.92) 5(11240.64,2873.23) 6(12071.53,1649.02) 7(12084.78,2102.76) 8(12124.96,2177.57) 11(11745.8,1926.3) 12(11925.92,2122.16)
  round 236.22 hole 125.98 paste+19.68: 10(893.77,641.74) 10(10244.15,641.74)
  round 177.17 hole 125.98 paste+19.68: 10(5566.99,2275.59)
  round 19.68 all layers, no hole: 75(14943.97,1862.2) 108(425.27,366.14) 111(5100.46,366.14) 119(14569.95,366.14) 120(15692,366.14)

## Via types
v1: diameter 23.62, hole 15.75, Top Layer to Bottom Layer, tented both sides, 2766 vias
v2: diameter 19.68, hole 11.81, Top Layer to Bottom Layer, tented both sides, 6 vias

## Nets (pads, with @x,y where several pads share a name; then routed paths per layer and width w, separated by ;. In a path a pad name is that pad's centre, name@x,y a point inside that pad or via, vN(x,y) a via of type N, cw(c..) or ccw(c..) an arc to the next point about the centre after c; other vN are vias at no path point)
1: pad.6 U1.3 | length 289.1
  Bottom Layer w7.87: U1.3@11880.59,1620.48 12042.99,1620.48 ; pad.6@12050.31,1644.73 cw(c12024.05,1639.43) 12042.99,1620.48 ; pad.6@12058.03,1646.29 cw(c12041.31,1642.92) 12053.37,1630.86 cw(c12065.43,1618.8) pad.6@12068.8,1635.52 ; pad.6@12067.25,1627.8 ccw(c12061.94,1601.53) 12042.99,1620.48 ; pad.6@12071.53,1649.02 12042.99,1620.48
2: 
3: 
4: 
A1: 
A2: 
A3: 
A4: 
BL0: LED1.B LED2.B LED3.B LED4.B LED5.B LED6.B LED7.B LED8.B LED9.B LED10.B LED11.B LED12.B LED13.B LED14.B LED15.B LED16.B RR2.2 | length 18671.3
  Top Layer w7.87: v1(226.02,4644.02) v1(3218.15,4644.02) v1(8454.37,4644.02) v1(9950.43,4644.02) v1(10698.46,4644.02) v1(11651.22,4644.02) v1(12399.25,4644.02) v1(13147.28,4644.02) ; v1@231.59,4638.45 cw(c245.03,4625.01) 245.03,4644.02 cw(c245.03,4663.03) v1@231.59,4649.59 ; v1@1716.52,4638.45 ccw(c1703.08,4625.01) 1703.08,4644.02 ccw(c1703.08,4663.03) v1@1716.52,4649.59 ; v1@1727.65,4638.45 cw(c1741.1,4625.01) 1741.1,4644.02 cw(c1741.1,4663.03) v1@1727.65,4649.59 ; v1@2464.55,4638.45 ccw(c2451.11,4625.01) 2451.11,4644.02 ccw(c2451.11,4663.03) v1@2464.55,4649.59 ; v1@2475.69,4638.45 cw(c2489.13,4625.01) 2489.13,4644.02 cw(c2489.13,4663.03) v1@2475.69,4649.59 ; v1@3212.58,4638.45 ccw(c3199.14,4625.01) 3199.14,4644.02 ccw(c3199.14,4663.03) v1@3212.58,4649.59 ; v1@3223.72,4638.45 cw(c3237.16,4625.01) 3237.16,4644.02 cw(c3237.16,4663.03) v1@3223.72,4649.59 ; v1@3960.61,4638.45 ccw(c3947.17,4625.01) 3947.17,4644.02 ccw(c3947.17,4663.03) v1@3960.61,4649.59 ; v1@3971.75,4638.45 cw(c3985.19,4625.01) 3985.19,4644.02 cw(c3985.19,4663.03) v1@3971.75,4649.59 ; v1@5082.66,4638.45 ccw(c5069.22,4625.01) 5069.22,4644.02 ccw(c5069.22,4663.03) v1@5082.66,4649.59 ; v1@5093.8,4638.45 cw(c5107.24,4625.01) 5107.24,4644.02 cw(c5107.24,4663.03) v1@5093.8,4649.59 ; v1@5830.69,4638.45 ccw(c5817.25,4625.01) 5817.25,4644.02 ccw(c5817.25,4663.03) v1@5830.69,4649.59 ; v1@5841.83,4638.45 cw(c5855.27,4625.01) 5855.27,4644.02 cw(c5855.27,4663.03) v1@5841.83,4649.59 ; v1@6578.72,4638.45 ccw(c6565.28,4625.01) 6565.28,4644.02 ccw(c6565.28,4663.03) v1@6578.72,4649.59 ; v1@6589.86,4638.45 cw(c6603.3,4625.01) 6603.3,4644.02 cw(c6603.3,4663.03) v1@6589.86,4649.59 ; v1@7326.75,4638.45 ccw(c7313.31,4625.01) 7313.31,4644.02 ccw(c7313.31,4663.03) v1@7326.75,4649.59 ; v1@7337.89,4638.45 cw(c7351.33,4625.01) 7351.33,4644.02 cw(c7351.33,4663.03) v1@7337.89,4649.59 ; v1@8448.8,4638.45 ccw(c8435.36,4625.01) 8435.36,4644.02 ccw(c8435.36,4663.03) v1@8448.8,4649.59 ; v1@8459.94,4638.45 cw(c8473.38,4625.01) 8473.38,4644.02 cw(c8473.38,4663.03) v1@8459.94,4649.59 ; v1@9196.83,4638.45 ccw(c9183.39,4625.01) 9183.39,4644.02 ccw(c9183.39,4663.03) v1@9196.83,4649.59 ; v1@9207.97,4638.45 cw(c9221.41,4625.01) 9221.41,4644.02 cw(c9221.41,4663.03) v1@9207.97,4649.59 ; v1@9944.87,4638.45 ccw(c9931.42,4625.01) 9931.42,4644.02 ccw(c9931.42,4663.03) v1@9944.87,4649.59 ; v1@9956,4638.45 cw(c9969.44,4625.01) 9969.44,4644.02 cw(c9969.44,4663.03) v1@9956,4649.59 ; v1@10692.9,4638.45 ccw(c10679.46,4625.01) 10679.46,4644.02 ccw(c10679.46,4663.03) v1@10692.9,4649.59 ; v1@10704.03,4638.45 cw(c10717.47,4625.01) 10717.47,4644.02 cw(c10717.47,4663.03) v1@10704.03,4649.59 ; v1@11645.65,4638.45 ccw(c11632.21,4625.01) 11632.21,4644.02 ccw(c11632.21,4663.03) v1@11645.65,4649.59 ; v1@11656.79,4638.45 cw(c11670.23,4625.01) 11670.23,4644.02 cw(c11670.23,4663.03) v1@11656.79,4649.59 ; v1@12393.68,4638.45 ccw(c12380.24,4625.01) 12380.24,4644.02 ccw(c12380.24,4663.03) v1@12393.68,4649.59 ; v1@12404.82,4638.45 cw(c12418.26,4625.01) 12418.26,4644.02 cw(c12418.26,4663.03) v1@12404.82,4649.59 ; 12870.35,4644.02 ccw(c12870.35,4663.15) v1@12883.88,4649.62 ; 12870.52,4644.02 cw(c12870.52,4625.13) v1@12883.88,4638.49 ; v1@12895.01,4638.49 cw(c12908.37,4625.13) 12908.37,4644.02 ; v1@12895.01,4649.62 ccw(c12908.54,4663.15) 12908.54,4644.02 ; v1@13141.72,4638.45 ccw(c13128.27,4625.01) 13128.27,4644.02 ccw(c13128.27,4663.03) v1@13141.72,4649.59
  Bottom Layer w7.87: v1@220.46,4638.45 cw(c207.05,4625.05) 226.01,4625.05 ; LED1.B@226.01,4539.57 v1(226.02,4644.02) ; 226.01,4624.97 cw(c245.07,4624.97) v1@231.59,4638.45 ; v1@1716.52,4638.45 cw(c1703.11,4625.05) 1722.07,4625.05 ; LED2.B@1722.07,4539.57 v1(1722.09,4644.02) ; 1722.07,4624.97 cw(c1741.13,4624.97) v1@1727.65,4638.45 ; v1@2464.55,4638.45 cw(c2451.15,4625.05) 2470.1,4625.05 ; LED3.B@2470.1,4539.57 v1(2470.12,4644.02) ; 2470.1,4624.97 cw(c2489.17,4624.97) v1@2475.69,4638.45 ; v1@3212.58,4638.45 cw(c3199.18,4625.05) 3218.13,4625.05 ; LED4.B@3218.13,4539.57 v1(3218.15,4644.02) ; 3218.13,4624.97 cw(c3237.2,4624.97) v1@3223.72,4638.45 ; v1@3960.61,4638.45 cw(c3947.21,4625.05) 3966.17,4625.05 ; LED5.B@3966.17,4539.57 v1(3966.18,4644.02) ; 3966.17,4624.97 cw(c3985.23,4624.97) v1@3971.75,4638.45 ; v1@5082.66,4638.45 cw(c5069.26,4625.05) 5088.21,4625.05 ; LED6.B@5088.21,4539.57 v1(5088.23,4644.02) ; 5088.21,4624.97 cw(c5107.28,4624.97) v1@5093.8,4638.45 ; v1@5830.69,4638.45 cw(c5817.29,4625.05) 5836.24,4625.05 ; LED7.B@5836.24,4539.57 v1@5836.24,4644.02 ; 5836.24,4624.97 cw(c5855.31,4624.97) v1@5841.83,4638.45 ; v1@6578.72,4638.45 cw(c6565.32,4625.05) 6584.28,4625.05 ; LED8.B@6584.28,4539.57 v1(6584.29,4644.02) ; 6584.28,4624.97 cw(c6603.34,4624.97) v1@6589.86,4638.45 ; v1@7326.75,4638.45 cw(c7313.35,4625.05) 7332.31,4625.05 ; LED9.B@7332.31,4539.57 v1(7332.32,4644.02) ; 7332.31,4624.97 cw(c7351.37,4624.97) v1@7337.89,4638.45 ; v1@8448.8,4638.45 cw(c8435.4,4625.05) 8454.35,4625.05 ; LED10.B@8454.35,4539.57 v1(8454.37,4644.02) ; 8454.35,4624.97 cw(c8473.42,4624.97) v1@8459.94,4638.45 ; v1@9196.83,4638.45 cw(c9183.43,4625.05) 9202.39,4625.05 ; LED11.B@9202.39,4539.57 v1(9202.4,4644.02) ; 9202.39,4624.97 cw(c9221.45,4624.97) v1@9207.97,4638.45 ; v1@9944.87,4638.45 cw(c9931.46,4625.05) 9950.42,4625.05 ; LED12.B@9950.42,4539.57 v1(9950.43,4644.02) ; 9950.42,4624.97 cw(c9969.48,4624.97) v1@9956,4638.45 ; v1@10692.9,4638.45 cw(c10679.49,4625.05) 10698.45,4625.05 ; LED13.B@10698.45,4539.57 v1@10698.45,4644.02 ; 10698.45,4624.97 cw(c10717.51,4624.97) v1@10704.03,4638.45 ; v1@11645.65,4638.45 cw(c11632.25,4625.05) 11651.21,4625.05 ; LED14.B@11651.21,4539.57 v1(11651.22,4644.02) ; 11651.21,4624.97 cw(c11670.27,4624.97) v1@11656.79,4638.45 ; v1@12393.68,4638.45 cw(c12380.28,4625.05) 12399.24,4625.05 ; LED15.B@12399.24,4539.57 v1(12399.25,4644.02) ; 12399.24,4624.97 cw(c12418.3,4624.97) v1@12404.82,4638.45 ; RR2.2@12609.76,2165.61 12609.76,2191.35 12609.76,2193.31 12617.07,2200.62 12653.64,2200.62 12889.45,2436.42 v1(12889.45,4644.06) ; v1@12883.88,4638.49 cw(c12870.44,4625.05) 12889.45,4625.05 cw(c12908.46,4625.05) v1@12895.01,4638.49 ; v1@13141.72,4638.45 cw(c13128.31,4625.05) 13147.27,4625.05 ; LED16.B@13147.27,4539.57 v1(13147.28,4644.02) ; 13147.27,4624.97 cw(c13166.33,4624.97) v1@13152.85,4638.45
  other v1: 5836.26,4644.02
BL1: LED17.B LED18.B LED19.B LED20.B LED21.B LED22.B LED23.B LED24.B LED25.B LED26.B LED27.B LED28.B LED29.B LED30.B LED31.B LED32.B LED33.B LED34.B LED35.B LED36.B LED37.B RR5.2 | length 23633.2
  Top Layer w7.87: v1(226.99,3640.64) 265.88,3679.53 v1(13651.26,3679.53) v1(16298.09,3679.53) ; v1@226.99,3648.52 ccw(c226.99,3667.53) 240.43,3654.09 ccw(c253.88,3640.64) v1@234.87,3640.64 ; 899.28,3679.54 ccw(c899.28,3711.19) v1@921.66,3688.81 ; v1@932.8,3688.81 ccw(c955.18,3711.19) 955.18,3679.54 ; 1636.58,3679.54 ccw(c1636.58,3713.87) v1@1660.85,3689.59 ; v1@1671.99,3689.59 ccw(c1696.27,3713.87) 1696.27,3679.54 ; 2394.53,3679.54 ccw(c2394.53,3714.12) v1@2418.99,3689.66 ; 2413.54,3679.54 ccw(c2413.54,3695.11) v1(2424.55,3684.1) ccw(c2435.57,3695.11) 2435.57,3679.54 ; v1@2430.12,3689.66 ccw(c2454.58,3714.12) 2454.58,3679.54 ; 3143.09,3679.54 ccw(c3143.09,3716.17) v1@3168.99,3690.26 ; 3162.1,3679.54 ccw(c3162.1,3697.16) v1(3174.56,3684.7) ccw(c3187.02,3697.16) 3187.02,3679.54 ; v1@3180.13,3690.26 ccw(c3206.03,3716.17) 3206.03,3679.54 ; 3905.48,3679.53 ccw(c3905.48,3712.02) v1@3928.45,3689.05 ; v1@3939.58,3689.05 ccw(c3962.55,3712.02) 3962.55,3679.53 ; 4643.43,3679.53 ccw(c4643.43,3711.98) v1@4666.37,3689.04 ; v1@4677.51,3689.04 ccw(c4700.45,3711.98) 4700.45,3679.53 ; 5399.34,3679.54 ccw(c5399.34,3710.96) v1@5421.56,3688.74 ; v1@5432.69,3688.74 ccw(c5454.91,3710.96) 5454.91,3679.54 ; 6152.74,3679.53 ccw(c6152.74,3708.67) v1@6173.34,3688.07 ; 6167.06,3679.53 cw(c6167.06,3670.65) v1@6173.34,3676.93 ; v1@6184.47,3676.93 cw(c6190.75,3670.65) 6190.75,3679.53 ; v1@6184.47,3688.07 ccw(c6205.08,3708.67) 6205.08,3679.53 ; 6890.05,3679.54 ccw(c6890.05,3715.21) v1@6915.28,3689.98 ; 6909.06,3679.54 ccw(c6909.06,3696.2) v1(6920.85,3684.42) ccw(c6932.63,3696.2) 6932.63,3679.54 ; v1@6926.42,3689.98 ccw(c6951.64,3715.21) 6951.64,3679.54 ; 7637.12,3679.53 ccw(c7637.12,3708.85) v1@7657.85,3688.12 ; 7651.69,3679.54 cw(c7651.69,3670.83) v1@7657.85,3676.99 ; v1@7668.99,3676.99 cw(c7675.14,3670.83) 7675.14,3679.54 ; v1@7668.99,3688.12 ccw(c7689.71,3708.85) 7689.71,3679.53 ; 8408.4,3679.54 cw(c8408.4,3660.34) v1@8421.97,3673.91 ; 8408.66,3679.53 ccw(c8408.66,3698.36) v1@8421.97,3685.05 ; v1@8433.11,3673.91 cw(c8446.68,3660.34) 8446.68,3679.54 ; v1@8433.11,3685.05 ccw(c8446.42,3698.36) 8446.42,3679.53 ; 9139.13,3679.54 cw(c9139.13,3660.19) v1@9152.81,3673.87 ; 9139.61,3679.54 ccw(c9139.61,3698.21) v1@9152.81,3685.01 ; v1@9163.95,3673.87 cw(c9177.63,3660.19) 9177.63,3679.54 ; v1@9163.95,3685.01 ccw(c9177.15,3698.21) 9177.15,3679.54 ; 10257.32,3679.53 cw(c10257.32,3660.18) v1@10271,3673.86 ; 10257.8,3679.53 ccw(c10257.8,3698.2) v1@10271,3684.99 ; v1@10282.14,3673.86 cw(c10295.82,3660.18) 10295.82,3679.53 ; v1@10282.14,3684.99 ccw(c10295.34,3698.2) 10295.34,3679.53 ; 11587.86,3679.54 cw(c11587.86,3659.7) v1@11601.89,3673.72 ; 11589.03,3679.54 ccw(c11589.03,3697.72) v1@11601.89,3684.86 ; v1@11613.02,3673.72 cw(c11627.05,3659.7) 11627.05,3679.54 ; v1@11613.02,3684.86 ccw(c11625.88,3697.72) 11625.88,3679.54 ; 12328.07,3679.54 cw(c12328.07,3660.28) v1@12341.68,3673.89 ; 12328.42,3679.54 ccw(c12328.42,3698.3) v1@12341.68,3685.03 ; v1@12352.82,3673.89 cw(c12366.44,3660.28) 12366.44,3679.54 ; v1@12352.82,3685.03 ccw(c12366.09,3698.3) 12366.09,3679.54 ; 13080.3,3679.54 ccw(c13080.3,3699.05) v1@13094.1,3685.25 ; 13081.01,3679.53 cw(c13081.01,3661.03) v1@13094.1,3674.11 ; v1@13105.23,3674.11 cw(c13118.32,3661.03) 13118.32,3679.53 ; v1@13105.23,3685.25 ccw(c13119.03,3699.05) 13119.03,3679.54 ; v1@13645.69,3673.97 ccw(c13632.25,3660.53) 13632.25,3679.54 ccw(c13632.25,3698.54) v1@13645.69,3685.1 ; v1@13656.83,3673.97 cw(c13670.27,3660.53) 13670.27,3679.54 cw(c13670.27,3698.54) v1@13656.83,3685.1 ; 14029.85,3679.54 cw(c14029.85,3660.39) v1@14043.38,3673.93 ; 14030.04,3679.54 ccw(c14030.04,3698.41) v1@14043.38,3685.06 ; v1@14054.52,3673.93 cw(c14068.06,3660.39) 14068.06,3679.54 ; v1@14054.52,3685.06 ccw(c14067.87,3698.41) 14067.87,3679.54 ; v1@14783.9,3673.96 ccw(c14770.46,3660.52) 14770.46,3679.53 ccw(c14770.46,3698.54) v1@14783.9,3685.1 ; v1@14795.03,3673.96 cw(c14808.48,3660.52) 14808.48,3679.53 cw(c14808.48,3698.54) v1@14795.03,3685.1 ; 15521.16,3679.54 cw(c15521.16,3660.45) v1@15534.66,3673.94 ; 15521.27,3679.53 ccw(c15521.27,3698.47) v1@15534.66,3685.08 ; v1@15545.79,3673.94 cw(c15559.29,3660.45) 15559.29,3679.54 ; v1@15545.79,3685.08 ccw(c15559.18,3698.47) 15559.18,3679.53 ; v1@16292.52,3673.97 ccw(c16279.08,3660.53) 16279.08,3679.54 ccw(c16279.08,3698.54) v1@16292.52,3685.1
  Bottom Layer w7.87: LED17.B@217.25,3600.49 ccw(c193.73,3624.02) 226.99,3624.02 ccw(c260.26,3624.02) LED17.B@236.74,3600.49 ; v1@221.42,3635.08 cw(c207.98,3621.63) 226.99,3621.63 cw(c246,3621.63) v1@232.56,3635.08 ; LED17.B@226.99,3590.75 v1(226.99,3640.64) ; v1@921.66,3677.67 cw(c908.22,3664.23) 927.23,3664.23 cw(c946.24,3664.23) v1@932.8,3677.67 ; v1(927.23,3683.24) 927.23,3625.21 961.69,3590.75 LED18.B@975.02,3590.75 ; 937.41,3615.03 cw(c913.13,3590.75) LED18.B@947.47,3590.75 ; 938.48,3613.96 ccw(c961.24,3636.73) LED18.B@961.24,3604.53 ; v1@1660.85,3678.46 cw(c1647.41,3665.01) 1666.42,3665.01 cw(c1685.43,3665.01) v1@1671.99,3678.46 ; v1(1666.42,3684.02) 1666.42,3633.49 1709.16,3590.75 LED19.B@1723.06,3590.75 ; 1685.56,3614.35 ccw(c1709.28,3638.07) LED19.B@1709.28,3604.53 ; 1685.83,3614.08 cw(c1662.5,3590.75) LED19.B@1695.5,3590.75 ; v1@2418.99,3678.53 cw(c2405.54,3665.09) 2424.55,3665.09 cw(c2443.56,3665.09) v1@2430.12,3678.53 ; v1(2424.55,3684.1) 2424.55,3623.6 2457.4,3590.75 LED20.B@2471.09,3590.75 ; 2433.72,3614.44 cw(c2410.03,3590.75) LED20.B@2443.53,3590.75 ; 2433.95,3614.2 ccw(c2457.31,3637.56) LED20.B@2457.31,3604.53 ; v1@3168.99,3679.13 cw(c3155.55,3665.69) 3174.56,3665.69 cw(c3193.57,3665.69) v1@3180.13,3679.13 ; v1(3174.56,3684.7) 3174.56,3622.29 3206.09,3590.75 LED21.B@3219.12,3590.75 ; 3181.28,3615.56 cw(c3156.47,3590.75) LED21.B@3191.56,3590.75 ; 3183.11,3613.74 ccw(c3205.34,3635.97) LED21.B@3205.34,3604.53 ; v1@3928.45,3677.91 cw(c3915.01,3664.47) 3934.02,3664.47 cw(c3953.03,3664.47) v1@3939.58,3677.91 ; 3934.02,3613.71 ccw(c3976.34,3613.71) LED22.B@3946.41,3583.79 ; 3934.02,3632.72 ccw(c3995.34,3632.72) LED22.B@3951.98,3589.36 ; 3934.02,3651.73 ccw(c4014.35,3651.73) LED22.B@3957.55,3594.93 ; v1(3934.02,3683.48) 3934.02,3609.45 ; LED22.B@3939.71,3592.59 ccw(c3919.83,3595.26) 3934.02,3609.45 ; LED22.B@3950.79,3604.29 cw(c3947.28,3622.72) 3934.02,3609.45 ; LED22.B@3967.15,3590.75 3952.72,3590.75 3934.02,3609.45 ; v1@4666.37,3677.9 cw(c4652.93,3664.46) 4671.94,3664.46 cw(c4690.95,3664.46) v1@4677.51,3677.9 ; v1(4671.94,3683.47) 4671.94,3620.12 4701.31,3590.75 LED23.B@4715.18,3590.75 ; 4677.72,3614.34 ccw(c4701.4,3638.02) LED23.B@4701.4,3604.53 ; 4677.94,3614.11 cw(c4654.58,3590.75) LED23.B@4687.62,3590.75 ; v1@5421.56,3677.6 cw(c5408.11,3664.16) 5427.12,3664.16 cw(c5446.13,3664.16) v1@5432.69,3677.6 ; v1(5427.12,3683.17) 5427.12,3613.08 ; LED24.B@5435.66,3591.28 ccw(c5406.46,3592.41) 5427.13,3613.07 ; LED24.B@5448.92,3604.52 cw(c5447.83,3633.78) 5427.13,3613.07 ; LED24.B@5463.21,3590.75 5449.45,3590.75 5427.12,3613.08 ; v1@6173.34,3676.93 cw(c6159.9,3663.49) 6178.91,3663.49 cw(c6197.92,3663.49) v1@6184.47,3676.93 ; v1(6178.91,3682.5) 6178.91,3612.36 ; 6179.15,3612.12 ccw(c6197.46,3630.43) LED25.B@6197.46,3604.53 ; LED25.B@6184.07,3593.99 ccw(c6165.12,3598.57) 6178.91,3612.36 ; LED25.B@6211.24,3590.75 6200.51,3590.75 6178.91,3612.36 ; v1@6915.28,3678.85 cw(c6901.84,3665.41) 6920.85,3665.41 cw(c6939.86,3665.41) v1@6926.42,3678.85 ; v1(6920.85,3684.42) 6920.85,3615.87 6945.97,3590.75 LED26.B@6959.28,3590.75 ; 6921.64,3615.07 cw(c6897.32,3590.75) LED26.B@6931.72,3590.75 ; 6922.77,3613.94 ccw(c6945.5,3636.66) LED26.B@6945.5,3604.53 ; v1@7657.85,3676.99 cw(c7644.41,3663.54) 7663.42,3663.54 cw(c7682.43,3663.54) v1@7668.99,3676.99 ; v1(7663.42,3682.55) 7663.42,3621.51 7694.18,3590.75 LED27.B@7707.31,3590.75 ; 7669.54,3615.39 cw(c7644.91,3590.75) LED27.B@7679.75,3590.75 ; 7671.12,3613.81 ccw(c7693.53,3636.22) LED27.B@7693.53,3604.53 ; v1@8421.97,3673.91 cw(c8408.53,3660.47) 8427.54,3660.47 cw(c8446.55,3660.47) v1@8433.11,3673.91 ; 8427.54,3619.85 ccw(c8470.66,3619.85) LED28.B@8440.17,3589.36 ; 8427.54,3638.86 ccw(c8489.67,3638.86) LED28.B@8445.74,3594.93 ; 8427.54,3657.87 ccw(c8508.68,3657.87) LED28.B@8451.3,3600.49 ; v1(8427.54,3679.48) 8427.54,3590.75 LED28.B@8455.34,3590.75 ; v1@9152.81,3673.87 cw(c9139.37,3660.43) 9158.38,3660.43 cw(c9177.39,3660.43) v1@9163.95,3673.87 ; v1(9158.38,3679.44) 9158.38,3622.48 9190.11,3590.75 LED29.B@9203.37,3590.75 ; 9165.7,3615.15 cw(c9141.3,3590.75) LED29.B@9175.81,3590.75 ; 9166.95,3613.91 ccw(c9189.59,3636.55) LED29.B@9189.59,3604.53 ; v1@10271,3673.86 cw(c10257.56,3660.42) 10276.57,3660.42 cw(c10295.58,3660.42) v1@10282.14,3673.86 ; v1(10276.57,3679.43) 10276.57,3626.19 10312.01,3590.75 LED30.B@10325.42,3590.75 ; 10287.85,3614.9 cw(c10263.7,3590.75) LED30.B@10297.86,3590.75 ; 10288.74,3614.01 ccw(c10311.64,3636.91) LED30.B@10311.64,3604.53 ; v1@11601.89,3673.72 cw(c11588.45,3660.28) 11607.46,3660.28 cw(c11626.47,3660.28) v1@11613.02,3673.72 ; v1(11607.46,3679.29) 11607.46,3619.4 11636.1,3590.75 LED31.B@11651.21,3590.75 ; v1@12341.68,3673.89 cw(c12328.24,3660.45) 12347.25,3660.45 cw(c12366.26,3660.45) v1@12352.82,3673.89 ; v1(12347.25,3679.46) 12347.25,3621.24 12377.74,3590.75 LED32.B@12392.35,3590.75 ; 12353.64,3614.86 ccw(c12378.57,3639.79) LED32.B@12378.57,3604.53 ; 12355.63,3612.86 cw(c12333.51,3590.75) 12364.79,3590.75 ; RR5.2@13003.47,2165.61 13003.47,2207.66 13016.99,2221.18 13414.36,2221.18 13631.85,2438.67 13631.85,2601.51 13577.44,2655.91 13577.44,3072.45 13666.11,3161.12 13666.11,3631.9 13651.26,3646.76 v1(13651.26,3679.53) ; v1@13094.1,3674.11 cw(c13080.66,3660.67) 13099.67,3660.67 cw(c13118.68,3660.67) v1@13105.23,3674.11 ; v1(13099.67,3679.68) 13099.67,3619.01 13127.93,3590.75 LED33.B@13140.38,3590.75 ; 13102.13,3616.55 cw(c13076.34,3590.75) 13112.82,3590.75 ; 13105.35,3613.33 ccw(c13126.6,3634.58) LED33.B@13126.6,3604.53 ; v1@13645.69,3673.97 cw(c13632.25,3660.53) 13651.26,3660.53 cw(c13670.27,3660.53) v1@13656.83,3673.97 ; v1@14043.38,3673.93 cw(c14029.94,3660.49) 14048.95,3660.49 cw(c14067.96,3660.49) v1@14054.52,3673.93 ; v1(14048.95,3679.5) 14048.95,3619.49 14077.7,3590.75 LED34.B@14091.17,3590.75 ; 14053.64,3614.8 cw(c14029.59,3590.75) 14063.61,3590.75 ; 14054.39,3614.05 ccw(c14077.39,3637.05) LED34.B@14077.39,3604.53 ; v1@14783.9,3673.96 cw(c14770.46,3660.52) 14789.47,3660.52 cw(c14808.48,3660.52) v1@14795.03,3673.96 ; v1(14789.47,3679.53) 14789.47,3626.67 14825.39,3590.75 LED35.B@14839.2,3590.75 ; 14801.84,3614.3 ccw(c14825.42,3637.87) LED35.B@14825.42,3604.53 ; 14801.92,3614.22 cw(c14778.45,3590.75) 14811.64,3590.75 ; v1@15534.66,3673.94 cw(c15521.22,3660.5) 15540.23,3660.5 cw(c15559.24,3660.5) v1@15545.79,3673.94 ; v1(15540.23,3679.51) 15540.23,3623.62 15573.09,3590.75 LED36.B@15592.15,3590.75 ; v1@16292.52,3673.97 cw(c16279.08,3660.53) 16298.09,3660.53 cw(c16317.1,3660.53) v1@16303.65,3673.97 ; v1(16298.09,3679.53) 16298.09,3618.9 16326.24,3590.75 LED37.B@16340.18,3590.75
